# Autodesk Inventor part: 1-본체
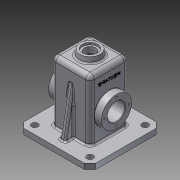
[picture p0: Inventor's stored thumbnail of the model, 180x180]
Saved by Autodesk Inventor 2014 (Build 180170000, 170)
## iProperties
Created: 2016-02
Part Number: 1-본체
Material: 알루미늄 6061
Document SubType Name: Modeling
Designer: Administrator
Density: 2.71 g/cm^3
Appearance: 알루미늄 - 평지
Mass: 932.81 g
Surface Area: 1043.48 cm^2
Volume: 344.21 cm^3
Author: Administrator
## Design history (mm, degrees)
sketch "스케치1"
  geometry: L1 (-35, 35)-(35, 35); L2 (35, 35)-(35, -35); L3 (35, -35)-(-35, -35); L4 (-35, -35)-(-35, 35); 3 further points
  constraints: 8 end point, 2 midpoint, 2 parallel, 1 horizontal, 1 horizontal alignment, 1 perpendicular, 1 vertical alignment
  dimensions: "d0" = 70 distance of L1.start L1.end; "d1" = 70 distance of L1.end L2.end
extrude "돌출1" new body sketch "스케치1" distance "d2" = 120; taper "d3" = 0 deg
sketch "스케치2"
  geometry: L1 (65, -65)-(-65, -65); L2 (-65, -65)-(-65, 65); L3 (-65, 65)-(65, 65); L4 (65, 65)-(65, -65); 3 further points
  constraints: 8 end point, 2 midpoint, 2 parallel, 2 perpendicular, 1 horizontal, 1 horizontal alignment, 1 vertical alignment
  dimensions: "d4" = 130 distance of L1.start L1.end
extrude "돌출3" join sketch "스케치2" distance "d7" = 10; taper "d8" = 0 deg
sketch "스케치4"
  geometry: C1 r 20 at (0, 0); 1 further point
  constraints: 1 centre point, 1 coincident
  dimensions: "d10" = 40 diameter of C1
extrude "돌출4" join sketch "스케치4" distance "d11" = 10; taper "d12" = -10 deg
sketch "스케치5"
  geometry: L1 (-50, 10)-(50, 10); L2 (50, 10)-(30.604, 120); L3 (30.604, 120)-(-30.604, 120); L4 (-30.604, 120)-(-50, 10); L5 (65, 10)-(-65, 10) reference; L6 (35, 120)-(-35, 120) reference; 3 further points
  constraints: 8 end point, 2 collinear, 2 midpoint, 2 vertical alignment, 1 equal length, 1 horizontal, 1 parallel
  dimensions: "d14" = 100 deg angle of L2 L5; "d15" = 15 distance of L5.start L1.end
sketch "스케치6"
  geometry: C1 r 27.5 at (0, 55); 1 further point
  constraints: 1 centre point, 1 vertical alignment
  dimensions: "d16" = 55 diameter of C1; "d17" = 55 distance of point (0, 0) C1.centre
extrude "돌출5" join sketch "스케치6" stored distance "d18" = 96; taper "d19" = 0 deg
sketch "스케치7"
  geometry: L1 (0, 0)-(-50, 50); L2 (65, 65)-(-65, 65) reference; L3 (-65, 65)-(-65, -65) reference
  constraints: 2 end point
  dimensions: "d21" = 15 horizontal distance of L2.end L1.end; "d22" = 15 distance from line of L1.end L3
hole "구멍1" sketch "스케치7" at (-50, 50) diameter "d23" = 12; stored, may be unused: countersink angle "d27" = 90 deg, drill point angle "d29" = 118 deg; dims "d24" = 6, "d25" = 4, "d26" = 2, "d28" = 8
extrude "돌출6" join sketch "스케치5" stored distance "d33" = 10; taper "d34" = 0 deg
sketch "스케치9"
  geometry: L1 (30, 115)-(-30, 115); L2 (-30, 115)-(-30, 0); L3 (-30, 0)-(30, 0); L4 (30, 0)-(30, 115); L5 (-35, 120)-(35, 120) reference; L6 (-35, 10)-(-35, 120) reference; 2 further points
  constraints: 8 end point, 2 midpoint, 2 parallel, 1 horizontal, 1 perpendicular, 1 vertical alignment
  dimensions: "d38" = 5 distance between parallel lines of L5 L1; "d39" = 5 distance between parallel lines of L6 L2
extrude "돌출7" cut sketch "스케치9" stored distance "d40" = 60; taper "d41" = 0 deg
sketch "스케치10"
  geometry: C1 r 27.5 at (60, 30) reference; C2 r 27.5 at (60, 30); 1 further point
  constraints: 1 centre point, 1 coincident
  dimensions: "d42" = 55 diameter of C2
extrude "돌출8" join sketch "스케치10" distance "d43" = 7; taper "d44" = -45 deg
sketch "스케치11"
  geometry: L1 (0, 0)-(22.5, 0); C1 r 27.5 at (0, 0) reference; 1 further point
  constraints: 2 end point, 1 horizontal
  dimensions: "d45" = 22.5 distance of L1.start L1.end
hole "구멍2" sketch "스케치11" at (22.5, 0) diameter "d46" = 3.242; stored, may be unused: countersink angle "d50" = 90 deg, drill point angle "d52" = 118 deg; dims "d47" = 8, "d48" = 4, "d49" = 2, "d51" = 10
hole "구멍3" diameter "d58" = 32; stored, may be unused: countersink angle "d62" = 90 deg, drill point angle "d64" = 118 deg; dims "d56" = 10, "d57" = 10, "d59" = 8, "d60" = 4, "d61" = 2, "d63" = 10
hole "구멍4" diameter "d67" = 21; stored, may be unused: countersink angle "d71" = 90 deg, drill point angle "d73" = 118 deg; dims "d65" = 10, "d66" = 10, "d68" = 8, "d69" = 28, "d70" = 4, "d72" = 10
fillet "모깎기1" dims "d74" = 8
fillet "모깎기2" dims "d75" = 8
chamfer "모따기1" distance "d76" = 10; stored, may be unused: second distance "d77" = 2, angle "d78" = 45 deg
fillet "모깎기3" dims "d79" = 3
fillet "모깎기4" dims "d80" = 3
fillet "모깎기5" dims "d81" = 3
fillet "모깎기6" dims "d82" = 3
fillet "모깎기7" dims "d83" = 3
fillet "모깎기8" dims "d84" = 3
fillet "모깎기9" dims "d85" = 0.5
fillet "모깎기10" dims "d86" = 0.5
chamfer "모따기2" distance "d87" = 1; stored, may be unused: second distance "d88" = 2, angle "d89" = 45 deg
sketch "스케치12"
  geometry: L1 (99, 62)-(0, 62) reference; L2 (-18, 8.763)-(-18, 45.237) reference; 2 further points
  constraints: 1 other
  dimensions: "d90" = 35 distance from line of L1 point (12, 27); "d91" = 30 distance from line of point (12, 27) L2
feature "엠보싱1" sketch "스케치12" dims "d0" = 70, "d1" = 70, "d92" = 0.5, "d93" = 0
node "솔리드1"
pattern_circular "원형 패턴1" dims angle "d31" = 360 deg
pattern_circular "원형 패턴2" dims angle "d54" = 360 deg
mirror "대칭1"
